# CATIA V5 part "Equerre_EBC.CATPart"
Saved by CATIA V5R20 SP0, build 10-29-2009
Part number: Equerre_EBC
Bounding box of the stored display mesh (mm): x 3 to 7, y -133.536 to 4.689, z -3.135 to 101.122
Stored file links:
  D:\Dropbox\IAO_2012\IAO_2012_753_jrecappe\jrecappe.zip\Equerre_EBC.CATPart
  D:\Dropbox\IAO_2012\IAO_2012_753_jrecappe\jrecappe.zip\Ass_skl_levier2bras.CATProduct
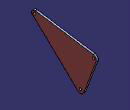
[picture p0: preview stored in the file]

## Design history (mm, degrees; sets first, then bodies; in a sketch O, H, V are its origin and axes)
Set1
  DatumPoint1 "Point E": linked copy from another document
  Point1 "PoinT B": linked copy from another document
  DatumPoint2 "Point C": linked copy from another document
Body1 (main body)
  Sketch1 on yz-plane, origin (0, 0, 0), H (0, 1, 0), V (0, 0, 1)
    point P1 (-126.023, 101.0539)
    line L1 (-126.023, 101.0539) -> (-2.0327, 82.2283)
    point P2 (-2.0327, 82.2283)
    line L2 (4.4043, 72.2926) -> (-22, 3)
    arc A1 centre (-3.2204, 74.4059) radius 7.9121 from (4.4043, 72.2926) to (-2.0327, 82.2283) ccw
    point P6 (-2.0327, 82.2283)
    arc A2 centre (-29.6268, 4.6621) radius 7.8058 from (-22, 3) to (-35, -1) cw
    arc A3 centre (-127.0038, 94.5944) radius 6.5335 from (-126.023, 101.0539) to (-133, 92) ccw
    point P11 (-126.023, 101.0539)
    line L3 (-35, -1) -> (-133, 92)
    circle A4 centre (-127.3306, 95.2723) radius 2.5
    point P12 (-127.3306, 95.2723)
    reference projected point E1 (-127.3306, 95.2723) from DatumPoint1
    circle A5 centre (-29.6225, 4.744) radius 2.5
    point P13 (-29.6225, 4.744)
    reference projected point E2 (-29.6225, 4.744) from Point1
    circle A6 centre (-2.039, 75.1322) radius 2.5
    point P14 (-2.039, 75.1322)
    reference projected point E3 (-2.039, 75.1322) from DatumPoint2
    coincidence: P6 L1, P1 P11, P2 P6, P12 E1, P13 E2, P14 E3
    tangency: A1 L1, A3 L1, L3 A2
  Pad1: profile Sketch1, direction (1, 0, 0), length 7, opposite side length -3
